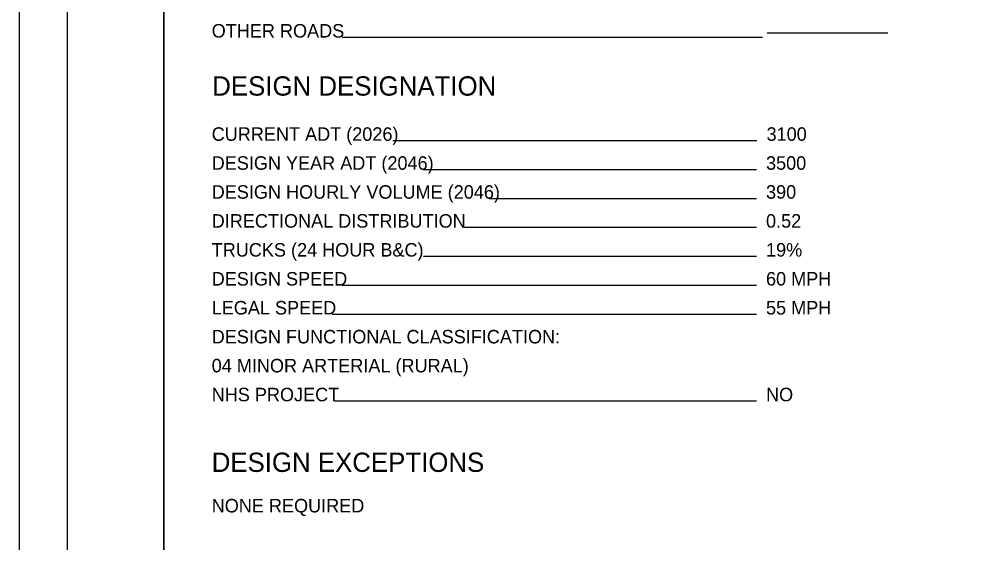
# Model space of a CAD drawing. Extents: x 0 to 34, y 0 to 22.
# Drawn here: x 0 to 9.93, y 5.64 to 11.07 of the extents above; entities that cross this region are included whole.
import ezdxf

# ---------------------------------------------------------------- set-up
doc = ezdxf.new("R2010")
doc.units = 0
for name, color, linetype in [('SH_Border', 7, 'Continuous'), ('SH_Cut_Line', 7, 'Continuous'), ('SH_Data', 7, 'Continuous'), ('SH_Text', 7, 'Continuous')]:
    doc.layers.add(name, color=color, linetype=linetype)

msp = doc.modelspace()

# ---------------------------------------------------------------- linework, layer by layer
at = {"layer": 'SH_Border'}
for points in [[(0.5, 21.5), (1.5, 21.5), (1.5, 0.5), (0.5, 0.5)], [(1.5, 21.5), (33.5, 21.5), (33.5, 0.5), (1.5, 0.5)]]:
    msp.add_lwpolyline(points, close=True, dxfattribs=at)
at = {"layer": 'SH_Cut_Line'}
msp.add_lwpolyline([(0, 0), (34, 0), (34, 22), (0, 22)], close=True, dxfattribs=at)
at = {"layer": 'SH_Data'}
for p, q in [((7.7, 10.8767), (3.3471, 10.8767)), ((9, 10.9223), (7.75, 10.9223)), ((7.6424, 9.8062), (3.871, 9.8062)), ((7.6368, 9.5062), (4.1885, 9.5062)), ((7.6368, 9.2062), (4.8723, 9.2062)), ((7.6368, 8.9062), (4.6037, 8.9062)), ((7.6368, 8.6062), (4.1885, 8.6062)), ((7.6368, 8.3062), (3.346, 8.3062)), ((7.6368, 8.0062), (3.2422, 8.0062)), ((7.6368, 7.1062), (3.2669, 7.1062))]:
    msp.add_line(p, q, dxfattribs=at)

# ---------------------------------------------------------------- texts
msp.add_text('DESIGN DESIGNATION', height=0.2, dxfattribs=at).set_placement((2, 10.2747))
at = {"layer": 'SH_Text'}
for s, height, p in [('OTHER ROADS', 0.14, (1.9944, 10.8767)), ('CURRENT ADT (2026)', 0.14, (1.9944, 9.8062)), ('3100', 0.14, (7.7424, 9.8062)), ('DESIGN YEAR ADT (2046)', 0.14, (1.9944, 9.5062)), ('3500', 0.14, (7.7368, 9.5062)), ('DESIGN HOURLY VOLUME (2046)', 0.14, (1.9944, 9.2062)), ('390', 0.14, (7.7368, 9.2062)), ('DIRECTIONAL DISTRIBUTION', 0.14, (1.9944, 8.9062)), ('0.52', 0.14, (7.7368, 8.9062)), ('TRUCKS (24 HOUR B&C)', 0.14, (1.9944, 8.6062)), ('19%', 0.14, (7.7368, 8.6062)), ('DESIGN SPEED', 0.14, (1.9944, 8.3062)), ('60 MPH', 0.14, (7.7368, 8.3062)), ('LEGAL SPEED', 0.14, (1.9944, 8.0062)), ('55 MPH', 0.14, (7.7368, 8.0062)), ('DESIGN FUNCTIONAL CLASSIFICATION:', 0.14, (1.9944, 7.7062)), ('04 MINOR ARTERIAL (RURAL)', 0.14, (1.9944, 7.4062)), ('NHS PROJECT', 0.14, (1.9944, 7.1062)), ('NO', 0.14, (7.7368, 7.1062)), ('DESIGN EXCEPTIONS', 0.2, (1.9944, 6.3744)), ('NONE REQUIRED', 0.14, (1.9944, 5.9544))]:
    msp.add_text(s, height=height, dxfattribs=at).set_placement(p)

doc.saveas('drawing.dxf')
